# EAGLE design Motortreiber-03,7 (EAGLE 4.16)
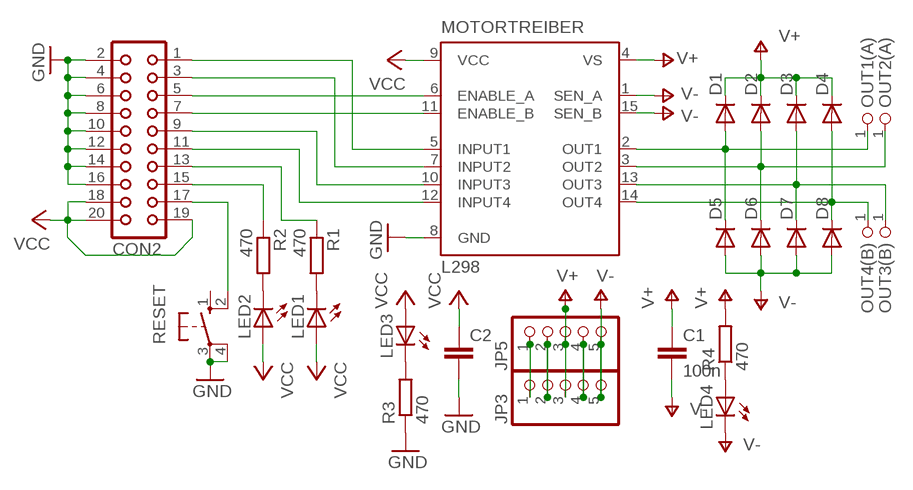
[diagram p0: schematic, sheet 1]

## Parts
C1  100n  C-EU050-030X075  [C050-030X075]
C2  C-EU050-025X075  [C050-025X075]
CON2  CON20  [CON20]
D1  DIODE-D-7.5  [D-7.5]
D2  DIODE-D-7.5  [D-7.5]
D3  DIODE-D-7.5  [D-7.5]
D4  DIODE-D-7.5  [D-7.5]
D5  DIODE-D-7.5  [D-7.5]
D6  DIODE-D-7.5  [D-7.5]
D7  DIODE-D-7.5  [D-7.5]
D8  DIODE-D-7.5  [D-7.5]
JP3  PINHD-1X5  [1X05]
JP5  PINHD-1X5  [1X05]
LED1  LED3MM  [LED3MM]
LED2  LED3MM  [LED3MM]
LED3  LED3MM  [LED3MM]
LED4  LED3MM  [LED3MM]
MOTORTREIBER  L298  [MULTIWATT-15]
OUT1(A)  PINHD-1X1  [1X01]
OUT2(A)  PINHD-1X1  [1X01]
OUT3(B)  PINHD-1X1  [1X01]
OUT4(B)  PINHD-1X1  [1X01]
R1  470  R-EU_0204/7  [0204/7]
R2  470  R-EU_0204/7  [0204/7]
R3  470  R-EU_0204/7  [0204/7]
R4  470  R-EU_0204/7  [0204/7]
RESET  10-XX  [B3F-10XX]

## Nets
GND: C2.2 CON2.2 CON2.4 CON2.6 CON2.8 CON2.10 CON2.12 CON2.14 CON2.16 MOTORTREIBER.8(GND) R3.1 RESET.3(P) RESET.4(P1)
L1´: D3.A D7.C MOTORTREIBER.13(OUT3) OUT3(B).1
L2´: D4.A D8.C MOTORTREIBER.14(OUT4) OUT4(B).1
N$1: CON2.5 MOTORTREIBER.6(ENABLE_A)
N$2: CON2.15 R2.1
N$3: CON2.7 MOTORTREIBER.11(ENABLE_B)
N$6: CON2.17 RESET.2(S1)
N$7: JP3.2 JP5.2
N$9: LED1.K(C) R1.2
N$10: LED2.K(C) R2.2
N$14: CON2.3 MOTORTREIBER.7(INPUT2)
N$15: CON2.1 MOTORTREIBER.5(INPUT1)
N$16: JP3.4 JP5.4
N$17: CON2.9 MOTORTREIBER.10(INPUT3)
N$18: CON2.11 MOTORTREIBER.12(INPUT4)
N$19: CON2.13 R1.1
N$21: LED3.K(C) R3.2
N$22: LED4.A R4.1
N$30: JP3.1 JP5.1
R1´: D1.A D5.C MOTORTREIBER.2(OUT1) OUT1(A).1
R2´: D2.A D6.C MOTORTREIBER.3(OUT2) OUT2(A).1
V+: C1.1 D1.C D2.C D3.C D4.C JP3.3 JP5.3 MOTORTREIBER.4(VS) R4.2
V-: C1.2 D5.A D6.A D7.A D8.A JP3.5 JP5.5 LED4.K(C) MOTORTREIBER.1(SEN_A) MOTORTREIBER.15(SEN_B)
VCC: C2.1 CON2.18 CON2.19 CON2.20 LED1.A LED2.A LED3.A MOTORTREIBER.9(VCC)
Unconnected: RESET.1(S)

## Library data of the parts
C1 C2 = rcl:C-EU: CAPACITOR, European symbol
CON2 = con-harting:CON20: CONNECTOR
D1-D8 = diode:DIODE-: DIODE
JP3 JP5 = pinhead:PINHD-1X5: PIN HEADER
LED1-LED4 = led:LED: LED
MOTORTREIBER = st-microelectronics:L298: DUAL FULL-BRIDGE DRIVER
OUT1(A) OUT2(A) OUT3(B) OUT4(B) = pinhead 02:PINHD-1X1: PIN HEADER
R1-R4 = rcl:R-EU_: RESISTOR, European symbol
RESET = switch-omron:10-XX: OMRON SWITCH

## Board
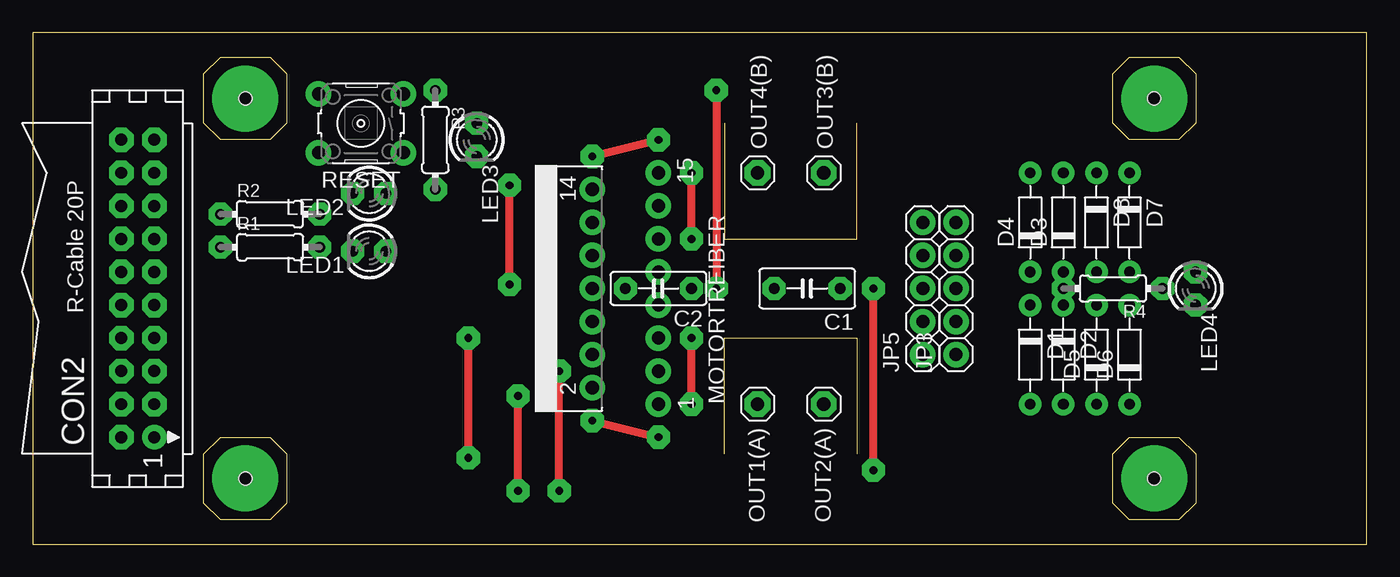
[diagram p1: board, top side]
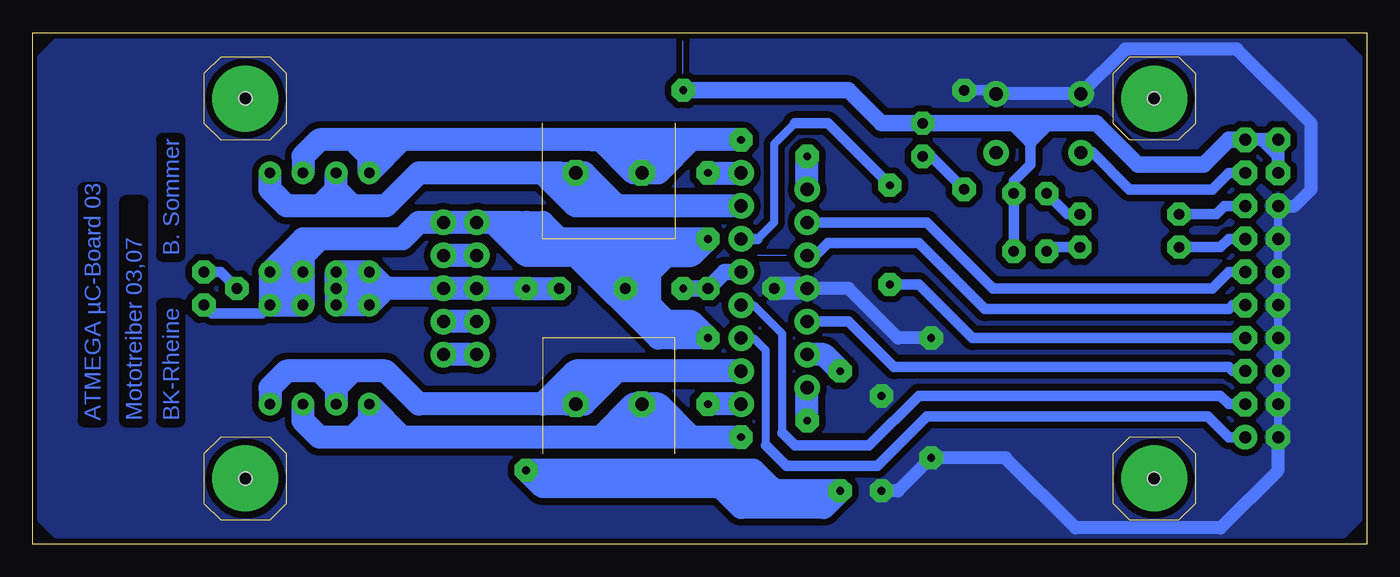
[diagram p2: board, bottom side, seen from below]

Size 102.54 x 39.36 mm. Coordinates in mm from the lower left corner, seen from the top.
Outline: 53.17,32.38 53.17,23.49 63.34,23.49 63.34,32.38
Outline: 53.17,6.98 53.17,15.87 63.34,15.87 63.34,6.98
Outline: 0,0 102.54,0 102.54,39.36 0,39.36 0,0
Outline: 14.44,37.46 18.25,37.46 19.52,36.19 19.52,32.38 18.25,31.11 14.44,31.11 13.17,32.38 13.17,36.19 14.44,37.46
Outline: 14.44,8.25 18.25,8.25 19.52,6.98 19.52,3.17 18.25,1.9 14.44,1.9 13.17,3.17 13.17,6.98 14.44,8.25
Outline: 84.29,37.46 88.1,37.46 89.37,36.19 89.37,32.38 88.1,31.11 84.29,31.11 83.02,32.38 83.02,36.19 84.29,37.46
Outline: 84.29,8.25 88.1,8.25 89.37,6.98 89.37,3.17 88.1,1.9 84.29,1.9 83.02,3.17 83.02,6.98 84.29,8.25
Copper layers (1*16): Top 0.035mm / dielectric 1.5mm / Bottom 0.035mm
Design rules "default": minimum track width 24mil, minimum drill 0.5mm, track to track 20mil, track to pad 24mil, pad to pad 24mil, via to via 24mil, smd to smd 0mil, copper to edge 0mil, drill to drill 1mil, minimum pad ring 19mil, minimum via ring 19mil, stop-mask expansion 4mil, vias tented up to drill 0mil, thermal gap 0mil
Holes 1.02 mm at 16.34,34.29 16.34,5.08 86.19,34.29 86.19,5.08

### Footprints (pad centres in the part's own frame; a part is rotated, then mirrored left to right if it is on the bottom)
C050-030X075 = drill 0.813 octagon: 1 -2.54,0; 2 2.54,0
C050-025X075 = drill 0.813 octagon: 1 -2.54,0; 2 2.54,0
CON20 = drill 0.914 round: 1 -11.43,-1.27 | drill 0.914 octagon: 2 -11.43,1.27; 3 -8.89,-1.27; 4 -8.89,1.27; 5 -6.35,-1.27; 6 -6.35,1.27; 7 -3.81,-1.27; 8 -3.81,1.27; 9 -1.27,-1.27; 10 -1.27,1.27; 11 1.27,-1.27; 12 1.27,1.27; 13 3.81,-1.27; 14 3.81,1.27; 15 6.35,-1.27; 16 6.35,1.27; 17 8.89,-1.27; 18 8.89,1.27; 19 11.43,-1.27; 20 11.43,1.27
D-7.5 = drill 0.813 long: A 3.81,0; C -3.81,0
1X05 = drill 1.016 long: 1 -5.08,0; 2 -2.54,0; 3 0,0; 4 2.54,0; 5 5.08,0
LED3MM = drill 0.813 octagon: A -1.27,0; K 1.27,0
MULTIWATT-15 = drill 1.016 long: 1 -8.89,-7.62; 2 -7.62,-2.54; 3 -6.35,-7.62; 4 -5.08,-2.54; 5 -3.81,-7.62; 6 -2.54,-2.54; 7 -1.27,-7.62; 8 0,-2.54; 9 1.27,-7.62; 10 2.54,-2.54; 11 3.81,-7.62; 12 5.08,-2.54; 13 6.35,-7.62; 14 7.62,-2.54; 15 8.89,-7.62
1X01 = drill 1.016 octagon: 1 0,0
0204/7 = drill 0.813 octagon: 1 -3.81,0; 2 3.81,0
B3F-10XX = drill 1.016 long: 1 -3.251,2.261; 2 3.251,2.261; 3 -3.251,-2.261; 4 3.251,-2.261

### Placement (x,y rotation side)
C1  59.52,19.68 180 top
C2  48.09,19.68 180 top
CON2  8.09,19.68 90 top
D1  76.67,14.6 270 top
D2  79.21,14.6 270 top
D3  79.21,24.76 90 top
D4  76.67,24.76 90 top
D5  81.75,14.6 90 top
D6  84.29,14.6 90 top
D7  84.29,24.76 270 top
D8  81.75,24.76 270 top
JP3  70.95,19.68 90 top
JP5  68.41,19.68 90 top
LED1  25.87,22.54 180 top
LED2  25.87,26.98 180 top
LED3  34.12,31.11 270 top
LED4  89.37,19.68 270 top
MOTORTREIBER  40.48,19.68 90 top
OUT1(A)  55.71,10.79 0 top
OUT2(A)  60.8,10.79 0 top
OUT3(B)  60.8,28.57 0 top
OUT4(B)  55.71,28.57 0 top
R1  18.25,22.86 0 top
R2  18.25,25.39 0 top
R3  30.95,31.11 270 top
R4  83.02,19.68 180 top
RESET  25.23,32.38 180 top

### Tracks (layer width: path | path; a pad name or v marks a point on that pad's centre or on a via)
GND  (via drill 0.6 pad 1.78)
  Top 0.61: v33.49,6.66 v33.49,15.87 | v37.3,4.12 v37.3,11.43
  Bottom 0.61: CON2.16 CON2.14 CON2.12 CON2.10 CON2.8 CON2.6 CON2.4 CON2.2
  Bottom 0.813: RESET.3 28.77,34.92 R3.1
  Bottom 1.016: MOTORTREIBER.8 39.84,19.68 36.03,15.87 v33.49,15.87 | CON2.16 5.55,26.03 4.28,27.3 4.28,32.38 10,38.1 18.57,38.1 22.02,34.64 | RESET.3 28.45,34.64 28.41,34.6 28.37,34.64 22.02,34.64 | 22.02,34.64 RESET.4 | CON2.2 6.82,5.71 11.27,1.27 22.38,1.27 27.77,6.66 v33.49,6.66 36.03,4.12 v37.3,4.12
  Bottom 1.778: MOTORTREIBER.8 C2.2
  pour Bottom: 1.74,38.73 100.8,38.73 102.07,37.46 102.07,1.9 100.8,0.63 1.74,0.63 0.47,1.9 0.47,37.46
L1´
  Bottom 1.778: 77.94,26.03 75.4,26.03 72.86,28.57 63.34,28.57 | 77.94,26.03 79.21,27.3 | 79.21,27.3 D3.A | D7.C 84.29,27.3 83.02,26.03 80.48,26.03 | 77.94,26.03 80.48,26.03 | 79.21,27.3 80.48,26.03 | 62.06,28.57 OUT3(B).1 60.16,28.57 57.62,26.03 56.98,26.03 | 62.06,28.57 63.34,28.57 | MOTORTREIBER.13 56.98,26.03 | 56.98,26.03 59.52,26.03 | 59.52,26.03 62.06,28.57 | 59.52,26.03 60.8,26.03 63.34,28.57
L2´  (via drill 0.6 pad 1.78)
  Top 0.61: v43.02,29.84 v48.09,31.11
  Bottom 1.778: MOTORTREIBER.14 v43.02,29.84 | 74.13,31.11 D4.A 76.67,29.84 | 76.67,31.11 76.67,29.84 | 74.13,31.11 76.67,31.11 | 76.67,31.11 77.94,31.11 | 76.67,29.84 77.94,31.11 | 77.94,31.11 80.48,31.11 81.75,29.84 D8.C | v48.09,31.11 51.91,31.11 | 51.91,31.11 54.45,28.57 OUT4(B).1 56.35,28.57 58.89,31.11 59.52,31.11 | 59.52,31.11 74.13,31.11 | 51.91,31.11 59.52,31.11 | 51.91,31.11 53.17,31.11 54.45,29.84 56.98,29.84
N$1
  Bottom 0.813: CON2.5 10.31,13.33 10.63,13.65 36.35,13.65 39.84,17.14 MOTORTREIBER.6
N$2
  Bottom 0.813: CON2.15 10.95,26.03 11.58,25.39 R2.1
N$3  (via drill 0.6 pad 1.78)
  Top 0.61: v36.66,20 v36.66,27.62
  Bottom 0.61: 46.82,23.49 45.55,24.76 45.55,30.79 43.97,32.38
  Bottom 0.813: 46.82,23.49 MOTORTREIBER.11 | 43.97,32.38 41.43,32.38 v36.66,27.62 | v36.66,20 34.44,20 30.31,15.87 CON2.7
N$4
  pour Bottom: 1.1,36.19 3.01,38.1 98.89,38.1 101.44,35.55 101.44,3.8 98.89,1.27 3.01,1.27 1.1,3.17
N$5
  Bottom 0: 52.54,36.19 52.54,38.73
N$6
  Bottom 0.813: CON2.17 10.63,28.57 11.9,27.3 18.25,27.3 21.11,30.16 22.06,30.16 22.02,30.12 RESET.2
N$7
  Bottom 1.778: JP5.2 JP3.2
N$8  (via drill 0.6 pad 5.08)
  other vias: 16.34,34.29
N$9
  Bottom 0.813: R1.2 24.28,22.86 LED1.K
N$10
  Bottom 0.813: R2.2 23.01,25.39 LED2.K
N$11  (via drill 0.6 pad 5.08)
  other vias: 16.34,5.08
N$12  (via drill 0.6 pad 5.08)
  other vias: 86.19,5.08
N$13  (via drill 0.6 pad 5.08)
  other vias: 86.19,34.29
N$14
  Bottom 0.61: MOTORTREIBER.7 47.14,18.41 44.92,16.19 44.92,8.57
  Bottom 0.813: 44.92,8.57 43.97,7.62 38.25,7.62 34.44,11.43 11.27,11.43 10.63,10.79 CON2.3
N$15
  Bottom 0.61: MOTORTREIBER.5 47.14,15.87 46.19,14.92 46.19,7.62
  Bottom 0.813: 46.19,7.62 44.6,6.03 37.62,6.03 33.81,9.84 12.22,9.84 10.63,8.25 CON2.1
N$16
  Bottom 1.778: JP5.4 JP3.4
N$17
  Bottom 0.61: 10.31,18.41 10.63,18.09 | 42.38,22.22 MOTORTREIBER.10
  Bottom 0.813: CON2.9 10.31,18.41 | 10.63,18.09 29.36,18.09 34.44,23.17 41.43,23.17 42.38,22.22
N$18
  Bottom 0.813: CON2.11 10.63,20.95 11.9,19.68 28.73,19.68 33.81,24.76 MOTORTREIBER.12
N$19
  Bottom 0.813: CON2.13 10.63,23.49 11.27,22.86 R1.1
N$20
  Bottom 0: 44.6,22.22 46.82,22.22
N$21
  Bottom 0.813: R3.2 33.49,29.84 LED3.K
N$22
  Bottom 0.813: R4.1 88.1,20.95 LED4.A
N$30
  Bottom 1.778: JP5.1 JP3.1
R1´  (via drill 0.6 pad 1.78)
  Top 0.61: v43.02,9.52 v48.09,8.25
  Bottom 1.778: v43.02,9.52 MOTORTREIBER.2 | 74.13,8.25 D1.A 76.67,9.52 | 76.67,8.25 76.67,9.52 | 74.13,8.25 76.67,8.25 | 76.67,8.25 77.94,8.25 | 77.94,8.25 80.48,8.25 81.75,9.52 D5.C | 76.67,9.52 77.94,8.25 | v48.09,8.25 51.91,8.25 | 51.91,8.25 53.17,8.25 | 53.17,8.25 OUT1(A).1 58.25,8.25 56.98,8.25 | 53.17,8.25 56.98,8.25 | 53.17,8.25 54.45,8.25 55.71,9.52 56.98,8.25 | 56.98,8.25 58.89,8.25 | 58.89,8.25 56.35,10.79 54.45,10.79 51.91,8.25 | 58.89,8.25 74.13,8.25
R2´
  Bottom 1.778: 77.94,13.33 75.4,13.33 72.86,10.79 63.34,10.79 | 77.94,13.33 79.21,12.06 | 79.21,12.06 D2.A | D6.C 84.29,12.06 83.02,13.33 80.48,13.33 | 79.21,12.06 80.48,13.33 | 77.94,13.33 80.48,13.33 | MOTORTREIBER.3 57.62,13.33 | 57.62,13.33 58.25,13.33 | 58.25,13.33 OUT2(A).1 | OUT2(A).1 61.43,10.79 | 61.43,10.79 63.34,10.79 | 58.25,13.33 58.89,13.33 | 61.43,10.79 58.89,13.33 | 57.62,13.33 60.16,10.79 | 60.16,10.79 OUT2(A).1 | 58.89,13.33 60.8,13.33 63.34,10.79 | 60.16,10.79 61.43,10.79
V+  (via drill 0.6 pad 1.78)
  Top 0.61: v40.48,4.12 v40.48,13.33 | v64.61,5.71 v64.61,19.68
  Bottom 1.778: v40.48,13.33 41.74,14.6 MOTORTREIBER.4 | 45.87,4.44 49.68,4.44 | 49.68,4.44 63.34,4.44 v64.61,5.71 47.14,5.71 45.87,4.44 | 75.4,19.68 JP3.3 JP5.3 v64.61,19.68 C1.1 | 75.4,19.68 R4.2 | R4.2 D3.C D4.C 75.4,19.68 | 75.4,19.68 D1.C D2.C R4.2 | 45.87,4.44 45.55,4.12 v40.48,4.12 41.74,2.85 48.09,2.85 49.68,4.44
V-  (via drill 0.6 pad 1.78)
  Top 0.61: v50.63,23.49 v50.63,28.57 | v50.63,10.79 v50.63,15.87
  Bottom 0.813: LED4.K 88.73,17.77 84.92,17.77 D6.A
  Bottom 1.778: v50.63,28.57 MOTORTREIBER.15 | MOTORTREIBER.1 v50.63,10.79 | 80.48,23.49 81.75,23.49 | 81.75,23.49 81.75,22.22 | 81.75,22.22 D8.A | D8.A D7.A | D8.A D5.A D6.A | D6.A 83.02,19.68 D7.A | 81.75,23.49 D7.A | D7.A D6.A | 80.48,23.49 74.13,23.49 72.86,24.76 JP3.5 JP5.5 67.14,24.76 | 80.48,23.49 81.75,22.22 | 59.52,22.22 C1.2 54.45,17.14 | 60.8,22.22 59.52,22.22 | 60.8,22.22 62.06,22.22 | 63.34,23.49 64.61,24.76 65.24,24.76 | 63.34,23.49 v50.63,23.49 | v50.63,23.49 62.06,23.49 63.34,24.76 | 63.34,23.49 63.34,24.76 | 62.06,22.22 63.34,23.49 | 62.06,22.22 62.7,22.22 | 62.7,22.22 64.61,22.22 67.14,24.76 | 65.24,24.76 67.14,24.76 | 65.24,24.76 63.34,24.76 | 53.17,15.87 54.45,17.14 | 53.17,15.87 v50.63,15.87 51.91,17.14 53.81,17.14 | 53.81,17.14 54.45,17.14 | 54.45,17.14 55.71,18.41 55.71,20.95 54.45,22.22 53.81,22.22 | v50.63,23.49 51.91,22.22 53.81,22.22 | 59.52,22.22 53.81,22.22 | 59.52,22.22 58.25,20.95 56.98,20.95 | 53.17,15.87 54.45,15.87 60.8,22.22 | 62.7,22.22 65.24,24.76 | 53.81,22.22 55.08,20.95 55.08,18.41 53.81,17.14
VCC  (via drill 0.6 pad 1.78)
  Top 0.61: v52.54,34.92 v52.54,19.68
  Bottom 0.813: 25.87,31.11 25.87,29.2 27.14,27.93 LED2.A LED1.A
  Bottom 1.016: 8.09,31.11 CON2.20 6.82,29.84 | CON2.18 6.82,29.84 | 6.82,29.84 8.09,31.11 | 8.09,31.11 CON2.19
  Bottom 1.27: MOTORTREIBER.9 49.37,20.95 C2.1 v52.54,19.68 | CON2.19 10.63,31.11 12.54,29.2 17.61,29.2 20.79,32.38 24.6,32.38 | 24.6,32.38 25.87,31.11 | 24.6,32.38 25.87,32.38 | 25.87,31.11 27.14,32.38 | 25.87,31.11 25.87,32.38 | 25.87,32.38 27.14,32.38 | 27.14,32.38 LED3.A 37.3,32.38 39.84,34.92 v52.54,34.92

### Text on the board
Bottom: B. Sommer | BK-Rheine | Mototreiber 03,07 | ATMEGA µC-Board 03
